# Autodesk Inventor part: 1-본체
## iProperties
Created: 2014-12
Part Number: 1-본체
Document SubType Name: Modeling
Designer: Administrator
Density: 2.71 g/cm^3
Material: 알루미늄-6061
Mass: 613.433 g
Surface Area: 665.172 cm^2
Volume: 226.359 cm^3
Author: Administrator
